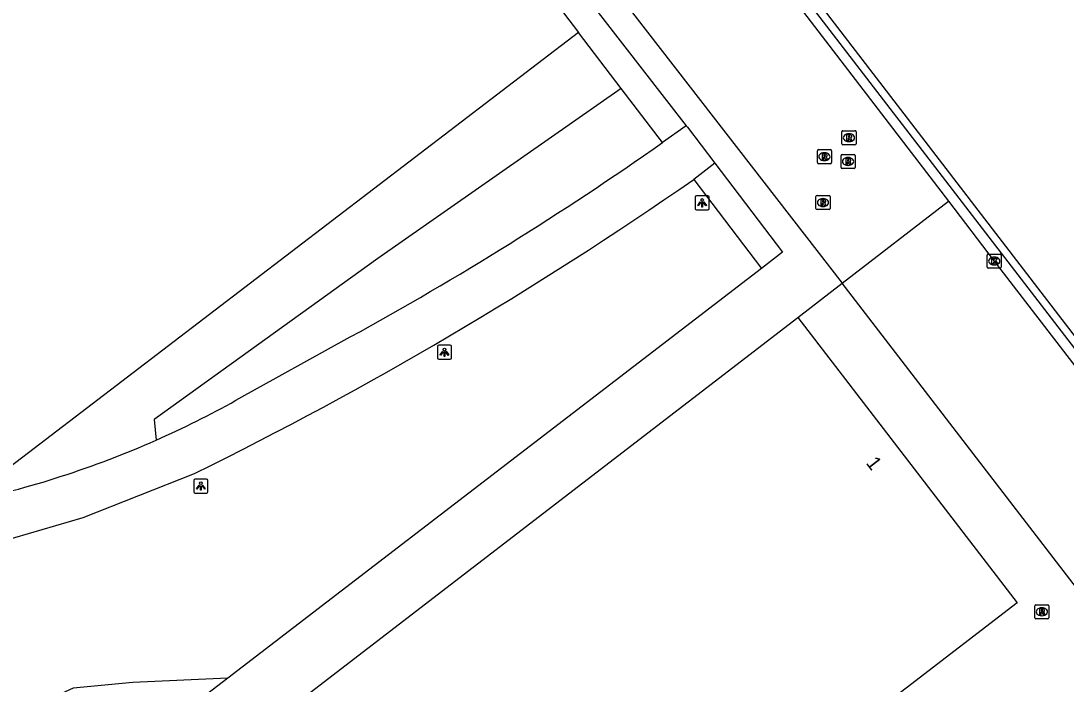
# Model space of a CAD drawing. Extents: x 155209 to 156823, y 385356 to 388482.
# Drawn here: x 156114.9 to 156189.2, y 385947.3 to 385994.4 of the extents above; entities that cross this region are included whole.
import ezdxf

# ---------------------------------------------------------------- set-up
doc = ezdxf.new("R2010")
doc.units = 0
for name, color, linetype in [('IMGEO_Groenvoorziening', 7, 'Continuous'), ('IMGEO_Haag', 7, 'Continuous'), ('IMGEO_Kolk', 7, 'Continuous'), ('IMGEO_Lichtpunt', 7, 'Continuous'), ('IMGEO_Loofbos', 7, 'Continuous'), ('IMGEO_Pand', 7, 'Continuous'), ('IMGEO_Pand_nummerreeks', 7, 'Continuous'), ('IMGEO_Rijbaan_lokaal_gesloten', 7, 'Continuous'), ('IMGEO_Rijbaan_lokaal_open', 7, 'Continuous'), ('IMGEO_Rioolput', 7, 'Continuous'), ('IMGEO_Voetpad_gesloten', 7, 'Continuous'), ('IMGEO_Voetpad_open', 7, 'Continuous')]:
    doc.layers.add(name, color=color, linetype=linetype)

msp = doc.modelspace()

# ---------------------------------------------------------------- linework, layer by layer
at = {"layer": 'IMGEO_Groenvoorziening'}
for points in [[(156157.568, 385989.652), (156140.278, 385977.551), (156124.385, 385966.102), (156124.515, 385964.645)], [(156129.607, 385947.725), (156122.858, 385947.408), (156118.61, 385947.023), (156110.425, 385943.255), (156106.886, 385945.056), (156102.938, 385946.083), (156096.563, 385945.599), (156088.771, 385944.146)]]:
    msp.add_lwpolyline(points, dxfattribs=at)
at = {"layer": 'IMGEO_Haag'}
for points in [[(156167.209, 386001.475), (156166.781, 386001.086), (156222.38, 385928.805), (156278.346, 385855.875), (156284.439, 385849.436), (156284.854, 385850.065)], [(156167.209, 386001.475), (156278.587, 385856.453), (156284.854, 385850.065)]]:
    msp.add_lwpolyline(points, dxfattribs=at)
at = {"layer": 'IMGEO_Kolk'}
for p, q in [((156183.589, 385976.95), (156183.589, 385977.802)), ((156183.664, 385977.876), (156184.516, 385977.876)), ((156184.077, 385977.656), (156184.102, 385977.656)), ((156184.59, 385977.802), (156184.59, 385976.95)), ((156184.516, 385976.876), (156183.664, 385976.876)), ((156184.1, 385977.096), (156184.075, 385977.096))]:
    msp.add_line(p, q, dxfattribs=at)
for points in [[(156183.589, 385976.95), (156183.589, 385977.802)], [(156183.664, 385977.876), (156184.516, 385977.876)], [(156183.91, 385977.576), (156184.033, 385977.576), (156184.033, 385977.425), (156184.163, 385977.576), (156184.327, 385977.576), (156184.181, 385977.425), (156184.334, 385977.176), (156184.182, 385977.176), (156184.097, 385977.34), (156184.033, 385977.273), (156184.033, 385977.176), (156183.91, 385977.176), (156183.91, 385977.576)], [(156184.59, 385977.802), (156184.59, 385976.95)], [(156184.516, 385976.876), (156183.664, 385976.876)]]:
    msp.add_lwpolyline(points, dxfattribs=at)
for centre, start, end in [((156183.666, 385977.8), 91.55205, 178.44795), ((156183.666, 385977.8), 91.55205, 178.44795), ((156184.514, 385977.8), 1.55205, 88.44795), ((156184.514, 385977.8), 1.55205, 88.44795), ((156183.666, 385976.952), 181.55205, 268.44795), ((156183.666, 385976.952), 181.55205, 268.44795), ((156184.514, 385976.952), 271.55205, 358.44795), ((156184.514, 385976.952), 271.55205, 358.44795)]:
    msp.add_arc(centre, 0.0765, start, end, dxfattribs=at)
for centre, major_axis, ratio, start_param, end_param in [((156184.076, 385977.376), (-0.387, 0.002), 0.722429, 4.712389, 7.853982), ((156184.101, 385977.376), (-0.39, 0.002), 0.717154, 1.570796, 4.712389)]:
    msp.add_ellipse(centre, major_axis=major_axis, ratio=ratio, start_param=start_param, end_param=end_param, dxfattribs=at)
at = {"layer": 'IMGEO_Lichtpunt'}
for p, q in [((156162.823, 385981.917), (156162.823, 385981.11)), ((156162.823, 385981.917), (156162.823, 385981.11)), ((156163.725, 385982.012), (156162.917, 385982.012)), ((156163.725, 385982.012), (156162.917, 385982.012)), ((156163.819, 385981.11), (156163.819, 385981.917)), ((156163.819, 385981.11), (156163.819, 385981.917)), ((156162.917, 385981.016), (156163.725, 385981.016)), ((156162.917, 385981.016), (156163.725, 385981.016)), ((156144.509, 385971.297), (156144.509, 385970.49)), ((156144.509, 385971.297), (156144.509, 385970.49)), ((156145.411, 385971.392), (156144.603, 385971.392)), ((156145.411, 385971.392), (156144.603, 385971.392)), ((156145.505, 385970.49), (156145.505, 385971.297)), ((156145.505, 385970.49), (156145.505, 385971.297)), ((156144.603, 385970.396), (156145.411, 385970.396)), ((156144.603, 385970.396), (156145.411, 385970.396)), ((156127.195, 385961.787), (156127.195, 385960.98)), ((156127.195, 385961.787), (156127.195, 385960.98)), ((156128.097, 385961.882), (156127.289, 385961.882)), ((156128.097, 385961.882), (156127.289, 385961.882)), ((156128.191, 385960.98), (156128.191, 385961.787)), ((156128.191, 385960.98), (156128.191, 385961.787)), ((156127.289, 385960.886), (156128.097, 385960.886)), ((156127.289, 385960.886), (156128.097, 385960.886))]:
    msp.add_line(p, q, dxfattribs=at)
for points in [[(156163.197, 385981.581), (156163.236, 385981.553), (156163.048, 385981.291), (156163.01, 385981.318), (156163.197, 385981.581)], [(156163.299, 385981.533), (156163.346, 385981.533), (156163.346, 385981.211), (156163.299, 385981.211), (156163.299, 385981.533)], [(156163.409, 385981.553), (156163.447, 385981.58), (156163.634, 385981.318), (156163.595, 385981.29), (156163.409, 385981.553)], [(156144.883, 385970.961), (156144.922, 385970.933), (156144.734, 385970.671), (156144.696, 385970.698), (156144.883, 385970.961)], [(156144.985, 385970.913), (156145.032, 385970.913), (156145.032, 385970.591), (156144.985, 385970.591), (156144.985, 385970.913)], [(156145.095, 385970.933), (156145.133, 385970.96), (156145.32, 385970.698), (156145.281, 385970.67), (156145.095, 385970.933)], [(156127.569, 385961.451), (156127.608, 385961.423), (156127.42, 385961.161), (156127.382, 385961.188), (156127.569, 385961.451)], [(156127.671, 385961.403), (156127.718, 385961.403), (156127.718, 385961.081), (156127.671, 385961.081), (156127.671, 385961.403)], [(156127.781, 385961.423), (156127.819, 385961.45), (156128.006, 385961.188), (156127.967, 385961.16), (156127.781, 385961.423)]]:
    msp.add_lwpolyline(points, dxfattribs=at)
for centre in [(156163.322, 385981.715), (156145.008, 385971.095), (156127.694, 385961.585)]:
    msp.add_circle(centre, 0.0994, dxfattribs=at)
for centre, start, end in [((156162.917, 385981.917), 90, 180), ((156162.917, 385981.917), 90, 180), ((156163.725, 385981.917), 0, 90), ((156163.725, 385981.917), 0, 90), ((156162.917, 385981.11), 180, 270), ((156162.917, 385981.11), 180, 270), ((156163.725, 385981.11), 270, 0), ((156163.725, 385981.11), 270, 360), ((156144.603, 385971.297), 90, 180), ((156144.603, 385971.297), 90, 180), ((156145.411, 385971.297), 0, 90), ((156145.411, 385971.297), 0, 90), ((156144.603, 385970.49), 180, 270), ((156144.603, 385970.49), 180, 270), ((156145.411, 385970.49), 270, 0), ((156145.411, 385970.49), 270, 360), ((156127.289, 385961.787), 90, 180), ((156127.289, 385961.787), 90, 180), ((156128.097, 385961.787), 0, 90), ((156128.097, 385961.787), 0, 90), ((156127.289, 385960.98), 180, 270), ((156127.289, 385960.98), 180, 270), ((156128.097, 385960.98), 270, 0), ((156128.097, 385960.98), 270, 360)]:
    msp.add_arc(centre, 0.0946, start, end, dxfattribs=at)
at = {"layer": 'IMGEO_Loofbos'}
msp.add_lwpolyline([(156154.535, 385993.632), (156110.792, 385960.218)], dxfattribs=at)
at = {"layer": 'IMGEO_Pand'}
for points in [[(155903.937, 385768.672), (155939.797, 385796.263), (156025.749, 385862.363), (156024.524, 385863.943), (156026.122, 385865.167), (156036.494, 385851.681), (156039.841, 385854.249), (156032.466, 385863.872), (156046.476, 385874.61), (156053.843, 385864.997), (156054.223, 385865.288), (156052.552, 385867.463), (156054.37, 385868.86), (156056.041, 385866.684), (156059.719, 385869.507), (156050.588, 385881.441), (156130.161, 385942.624), (156129.815, 385943.105), (156131.406, 385944.305), (156131.765, 385943.857), (156170.127, 385973.357)], [(156170.127, 385973.357), (156185.717, 385953.089), (156146.274, 385922.751), (156150.528, 385917.222), (156156.102, 385921.509), (156164.09, 385911.123), (156158.516, 385906.837), (156160.857, 385903.793), (156200.3, 385934.128), (156216.362, 385913.247), (156216.482, 385913.09), (156177.035, 385882.729), (156191.619, 385863.794), (156231.059, 385894.15), (156268.199, 385845.897), (156263.99, 385842.658), (156257.683, 385850.853), (156257.129, 385850.426), (156242.076, 385838.841), (156248.384, 385830.646), (156257.534, 385818.758), (156233.747, 385800.481), (156245.945, 385784.612), (156210.26, 385757.191)]]:
    msp.add_lwpolyline(points, dxfattribs=at)
at = {"layer": 'IMGEO_Rijbaan_lokaal_gesloten'}
for points in [[(156173.28, 385975.806), (156180.839, 385981.624)], [(156180.839, 385981.624), (156184.09, 385977.376), (156195.93, 385961.982), (156207.756, 385946.593), (156219.573, 385931.238), (156231.41, 385915.868), (156241.752, 385902.4), (156255.401, 385884.633), (156266.626, 385870.03), (156277.503, 385855.777), (156277.531, 385855.74)], [(156170.127, 385973.357), (156173.28, 385975.806)], [(156185.206, 385706.395), (156187.634, 385703.237), (156202.592, 385714.779), (156231.045, 385736.66), (156223.99, 385745.863), (156233.766, 385753.388), (156228.894, 385759.732), (156239.22, 385767.734), (156235.908, 385771.977), (156251.441, 385783.91), (156247.701, 385788.833), (156247.412, 385789.224), (156244.172, 385793.446), (156251.992, 385799.487), (156247.187, 385805.769), (156263.096, 385818.018), (156253.997, 385829.921), (156273.756, 385845.152), (156173.28, 385975.806)]]:
    msp.add_lwpolyline(points, dxfattribs=at)
at = {"layer": 'IMGEO_Rijbaan_lokaal_open'}
for points in [[(156176.524, 386026.479), (156150.284, 386005.616), (156156.897, 385996.959), (156157.631, 385995.998), (156173.28, 385975.806)], [(156184.674, 386017.186), (156177.537, 386011.492), (156166.201, 386002.568), (156165.304, 386001.86), (156168.669, 385997.526), (156180.839, 385981.624)]]:
    msp.add_lwpolyline(points, dxfattribs=at)
at = {"layer": 'IMGEO_Rioolput'}
for p, q in [((156173.261, 385985.717), (156173.261, 385986.569)), ((156173.336, 385986.643), (156174.188, 385986.643)), ((156174.262, 385986.569), (156174.262, 385985.717)), ((156173.772, 385985.863), (156173.747, 385985.863)), ((156173.749, 385986.423), (156173.774, 385986.423)), ((156171.515, 385984.37), (156171.515, 385985.222)), ((156171.59, 385985.296), (156172.442, 385985.296)), ((156172.003, 385985.076), (156172.028, 385985.076)), ((156172.516, 385985.222), (156172.516, 385984.37)), ((156174.188, 385985.643), (156173.336, 385985.643)), ((156172.442, 385984.296), (156171.59, 385984.296)), ((156172.026, 385984.516), (156172.001, 385984.516)), ((156173.196, 385984.031), (156173.196, 385984.883)), ((156173.271, 385984.957), (156174.123, 385984.957)), ((156173.684, 385984.737), (156173.709, 385984.737)), ((156174.197, 385984.883), (156174.197, 385984.031)), ((156174.123, 385983.957), (156173.271, 385983.957)), ((156173.707, 385984.177), (156173.682, 385984.177)), ((156171.491, 385982.033), (156172.343, 385982.033)), ((156171.416, 385981.107), (156171.416, 385981.959)), ((156171.904, 385981.813), (156171.929, 385981.813)), ((156172.417, 385981.959), (156172.417, 385981.107)), ((156172.343, 385981.033), (156171.491, 385981.033)), ((156171.927, 385981.253), (156171.902, 385981.253)), ((156186.973, 385952.017), (156186.973, 385952.869)), ((156187.048, 385952.943), (156187.9, 385952.943)), ((156187.461, 385952.723), (156187.486, 385952.723)), ((156187.974, 385952.869), (156187.974, 385952.017)), ((156187.9, 385951.943), (156187.048, 385951.943)), ((156187.484, 385952.163), (156187.459, 385952.163))]:
    msp.add_line(p, q, dxfattribs=at)
for points in [[(156173.261, 385985.717), (156173.261, 385986.569)], [(156173.336, 385986.643), (156174.188, 385986.643)], [(156174.262, 385986.569), (156174.262, 385985.717)], [(156173.85, 385986.341), (156173.598, 385986.343), (156173.598, 385985.943)], [(156173.598, 385985.943), (156173.722, 385985.943), (156173.722, 385986.105), (156173.733, 385986.105)], [(156173.776, 385986.262), (156173.722, 385986.262), (156173.722, 385986.181)], [(156173.722, 385986.181), (156173.774, 385986.181)], [(156173.78, 385986.076), (156173.851, 385985.943), (156173.991, 385985.943), (156173.926, 385986.069)], [(156171.515, 385984.37), (156171.515, 385985.222)], [(156171.59, 385985.296), (156172.442, 385985.296)], [(156172.104, 385984.994), (156171.852, 385984.996), (156171.852, 385984.596)], [(156172.516, 385985.222), (156172.516, 385984.37)], [(156174.188, 385985.643), (156173.336, 385985.643)], [(156172.442, 385984.296), (156171.59, 385984.296)], [(156171.852, 385984.596), (156171.976, 385984.596), (156171.976, 385984.758), (156171.987, 385984.758)], [(156172.03, 385984.915), (156171.976, 385984.915), (156171.976, 385984.834)], [(156171.976, 385984.834), (156172.028, 385984.834)], [(156172.034, 385984.729), (156172.105, 385984.596), (156172.245, 385984.596), (156172.18, 385984.722)], [(156173.196, 385984.031), (156173.196, 385984.883)], [(156173.271, 385984.957), (156174.123, 385984.957)], [(156173.785, 385984.655), (156173.533, 385984.657), (156173.533, 385984.257)], [(156173.533, 385984.257), (156173.657, 385984.257), (156173.657, 385984.419), (156173.668, 385984.419)], [(156173.711, 385984.576), (156173.657, 385984.576), (156173.657, 385984.495)], [(156173.657, 385984.495), (156173.709, 385984.495)], [(156173.715, 385984.39), (156173.786, 385984.257), (156173.926, 385984.257), (156173.861, 385984.383)], [(156174.197, 385984.883), (156174.197, 385984.031)], [(156174.123, 385983.957), (156173.271, 385983.957)], [(156171.491, 385982.033), (156172.343, 385982.033)], [(156171.416, 385981.107), (156171.416, 385981.959)], [(156172.005, 385981.731), (156171.753, 385981.733), (156171.753, 385981.333)], [(156171.753, 385981.333), (156171.877, 385981.333), (156171.877, 385981.495), (156171.888, 385981.495)], [(156171.931, 385981.652), (156171.877, 385981.652), (156171.877, 385981.571)], [(156171.877, 385981.571), (156171.929, 385981.571)], [(156171.935, 385981.466), (156172.006, 385981.333), (156172.146, 385981.333), (156172.081, 385981.459)], [(156172.417, 385981.959), (156172.417, 385981.107)], [(156172.343, 385981.033), (156171.491, 385981.033)], [(156186.973, 385952.017), (156186.973, 385952.869)], [(156187.048, 385952.943), (156187.9, 385952.943)], [(156187.562, 385952.641), (156187.31, 385952.643), (156187.31, 385952.243)], [(156187.31, 385952.243), (156187.434, 385952.243), (156187.434, 385952.405), (156187.445, 385952.405)], [(156187.488, 385952.562), (156187.434, 385952.562), (156187.434, 385952.481)], [(156187.434, 385952.481), (156187.486, 385952.481)], [(156187.492, 385952.376), (156187.563, 385952.243), (156187.703, 385952.243), (156187.638, 385952.369)], [(156187.974, 385952.869), (156187.974, 385952.017)], [(156187.9, 385951.943), (156187.048, 385951.943)]]:
    msp.add_lwpolyline(points, dxfattribs=at)
for centre, radius, start, end in [((156173.338, 385986.567), 0.0765, 91.55205, 178.44795), ((156173.338, 385986.567), 0.0765, 91.55205, 178.44795), ((156174.186, 385986.567), 0.0765, 1.55205, 88.44795), ((156174.186, 385986.567), 0.0765, 1.55205, 88.44795), ((156173.732, 385986.052), 0.0533, 26.02933, 88.69889), ((156173.758, 385986.37), 0.19, 274.7715, 282.96867), ((156173.782, 385986.166), 0.0964, 77.00612, 93.18647), ((156173.796, 385986.223), 0.0378, 276.66336, 79.67722), ((156173.849, 385986.231), 0.109, 350.36119, 89.41601), ((156173.847, 385986.231), 0.112, 277.58423, 350.98172), ((156173.831, 385986.016), 0.108, 29.51342, 73.79051), ((156171.592, 385985.22), 0.0765, 91.55205, 178.44795), ((156171.592, 385985.22), 0.0765, 91.55205, 178.44795), ((156172.44, 385985.22), 0.0765, 1.55205, 88.44795), ((156172.44, 385985.22), 0.0765, 1.55205, 88.44795), ((156173.338, 385985.719), 0.0765, 181.55205, 268.44795), ((156173.338, 385985.719), 0.0765, 181.55205, 268.44795), ((156174.186, 385985.719), 0.0765, 271.55205, 358.44795), ((156174.186, 385985.719), 0.0765, 271.55205, 358.44795), ((156171.592, 385984.372), 0.0765, 181.55205, 268.44795), ((156171.592, 385984.372), 0.0765, 181.55205, 268.44795), ((156171.986, 385984.705), 0.0533, 26.02933, 88.69889), ((156172.012, 385985.023), 0.19, 274.7715, 282.96867), ((156172.036, 385984.819), 0.0964, 77.00612, 93.18647), ((156172.05, 385984.876), 0.0378, 276.66336, 79.67722), ((156172.103, 385984.884), 0.109, 350.36119, 89.41601), ((156172.101, 385984.884), 0.112, 277.58423, 350.98172), ((156172.085, 385984.669), 0.108, 29.51342, 73.79051), ((156172.44, 385984.372), 0.0765, 271.55205, 358.44795), ((156172.44, 385984.372), 0.0765, 271.55205, 358.44795), ((156173.273, 385984.881), 0.0765, 91.55205, 178.44795), ((156173.273, 385984.881), 0.0765, 91.55205, 178.44795), ((156173.667, 385984.366), 0.0533, 26.02933, 88.69889), ((156173.693, 385984.684), 0.19, 274.7715, 282.96867), ((156173.717, 385984.48), 0.0964, 77.00612, 93.18647), ((156173.731, 385984.537), 0.0378, 276.66336, 79.67722), ((156173.784, 385984.545), 0.109, 350.36119, 89.41601), ((156173.782, 385984.545), 0.112, 277.58423, 350.98172), ((156173.766, 385984.33), 0.108, 29.51342, 73.79051), ((156174.121, 385984.881), 0.0765, 1.55205, 88.44795), ((156174.121, 385984.881), 0.0765, 1.55205, 88.44795), ((156173.273, 385984.033), 0.0765, 181.55205, 268.44795), ((156173.273, 385984.033), 0.0765, 181.55205, 268.44795), ((156174.121, 385984.033), 0.0765, 271.55205, 358.44795), ((156174.121, 385984.033), 0.0765, 271.55205, 358.44795), ((156171.493, 385981.957), 0.0765, 91.55205, 178.44795), ((156171.493, 385981.957), 0.0765, 91.55205, 178.44795), ((156172.341, 385981.957), 0.0765, 1.55205, 88.44795), ((156172.341, 385981.957), 0.0765, 1.55205, 88.44795), ((156171.887, 385981.442), 0.0533, 26.02933, 88.69889), ((156171.913, 385981.76), 0.19, 274.7715, 282.96867), ((156171.937, 385981.556), 0.0964, 77.00612, 93.18647), ((156171.951, 385981.613), 0.0378, 276.66336, 79.67722), ((156172.004, 385981.621), 0.109, 350.36119, 89.41601), ((156172.002, 385981.621), 0.112, 277.58423, 350.98172), ((156171.986, 385981.406), 0.108, 29.51342, 73.79051), ((156171.493, 385981.109), 0.0765, 181.55205, 268.44795), ((156171.493, 385981.109), 0.0765, 181.55205, 268.44795), ((156172.341, 385981.109), 0.0765, 271.55205, 358.44795), ((156172.341, 385981.109), 0.0765, 271.55205, 358.44795), ((156187.05, 385952.867), 0.0765, 91.55205, 178.44795), ((156187.05, 385952.867), 0.0765, 91.55205, 178.44795), ((156187.444, 385952.352), 0.0533, 26.02933, 88.69889), ((156187.47, 385952.67), 0.19, 274.7715, 282.96867), ((156187.494, 385952.466), 0.0964, 77.00612, 93.18647), ((156187.508, 385952.523), 0.0378, 276.66336, 79.67722), ((156187.561, 385952.531), 0.109, 350.36119, 89.41601), ((156187.559, 385952.531), 0.112, 277.58423, 350.98172), ((156187.543, 385952.316), 0.108, 29.51342, 73.79051), ((156187.898, 385952.867), 0.0765, 1.55205, 88.44795), ((156187.898, 385952.867), 0.0765, 1.55205, 88.44795), ((156187.05, 385952.019), 0.0765, 181.55205, 268.44795), ((156187.05, 385952.019), 0.0765, 181.55205, 268.44795), ((156187.898, 385952.019), 0.0765, 271.55205, 358.44795), ((156187.898, 385952.019), 0.0765, 271.55205, 358.44795)]:
    msp.add_arc(centre, radius, start, end, dxfattribs=at)
for centre, major_axis, ratio, start_param, end_param in [((156173.748, 385986.143), (-0.387, 0.002), 0.722429, 4.712389, 7.853982), ((156173.773, 385986.143), (-0.39, 0.002), 0.717154, 1.570796, 4.712389), ((156172.002, 385984.796), (-0.387, 0.002), 0.722429, 4.712389, 7.853982), ((156172.027, 385984.796), (-0.39, 0.002), 0.717154, 1.570796, 4.712389), ((156173.683, 385984.457), (-0.387, 0.002), 0.722429, 4.712389, 7.853982), ((156173.708, 385984.457), (-0.39, 0.002), 0.717154, 1.570796, 4.712389), ((156171.903, 385981.533), (-0.387, 0.002), 0.722429, 4.712389, 7.853982), ((156171.928, 385981.533), (-0.39, 0.002), 0.717154, 1.570796, 4.712389), ((156187.46, 385952.443), (-0.387, 0.002), 0.722429, 4.712389, 7.853982), ((156187.485, 385952.443), (-0.39, 0.002), 0.717154, 1.570796, 4.712389)]:
    msp.add_ellipse(centre, major_axis=major_axis, ratio=ratio, start_param=start_param, end_param=end_param, dxfattribs=at)
at = {"layer": 'IMGEO_Voetpad_gesloten'}
for points in [[(156162.197, 385986.99), (156160.509, 385985.793)], [(156162.197, 385986.99), (156162.28, 385986.884), (156164.223, 385984.332)], [(156164.223, 385984.332), (156162.729, 385983.183)], [(156130.189, 385967.476), (156138.317, 385971.979)], [(156113.496, 385957.432), (156119.321, 385959.145), (156127.24, 385962.271)]]:
    msp.add_lwpolyline(points, dxfattribs=at)
for centre, radius, start, end in [((156023.199, 386181.648), 239.193, 298.76895, 305.03364), ((156006.38, 386207.947), 273.795, 296.19475, 304.82294), ((156096.586, 386027.723), 68.985, 293.88235, 299.15078), ((156096.616, 386027.646), 68.902, 281.87329, 293.88581)]:
    msp.add_arc(centre, radius, start, end, dxfattribs=at)
at = {"layer": 'IMGEO_Voetpad_open'}
for points in [[(156173.258, 386028.793), (156144.769, 386006.447), (156154.535, 385993.632)], [(156174.878, 386027.645), (156147.591, 386005.96), (156155.384, 385995.757), (156156.096, 385994.825), (156162.197, 385986.99)], [(156157.568, 385989.652), (156154.535, 385993.632)], [(156160.509, 385985.793), (156157.568, 385989.652)], [(156164.223, 385984.332), (156169.049, 385978.012), (156167.554, 385976.836)], [(156162.729, 385983.183), (156167.554, 385976.836)], [(156167.554, 385976.836), (156129.607, 385947.725)], [(156129.607, 385947.725), (156115.909, 385937.216)]]:
    msp.add_lwpolyline(points, dxfattribs=at)

# ---------------------------------------------------------------- texts
at = {"layer": 'IMGEO_Pand_nummerreeks'}
msp.add_text('1', height=1, rotation=307.56863, dxfattribs=at).set_placement((156174.935, 385963.004))

doc.saveas('drawing.dxf')
